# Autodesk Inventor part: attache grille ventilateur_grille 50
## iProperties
Created: 2011-01
Part Number: attache grille ventilateur_grille 50
Document SubType Name: Modeling
Designer: eric
Density: 1 g/cm^3
Mass: 0.21185 g
Surface Area: 5.33646 cm^2
Volume: 0.21185 cm^3
Author: eric
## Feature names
1. Base1
